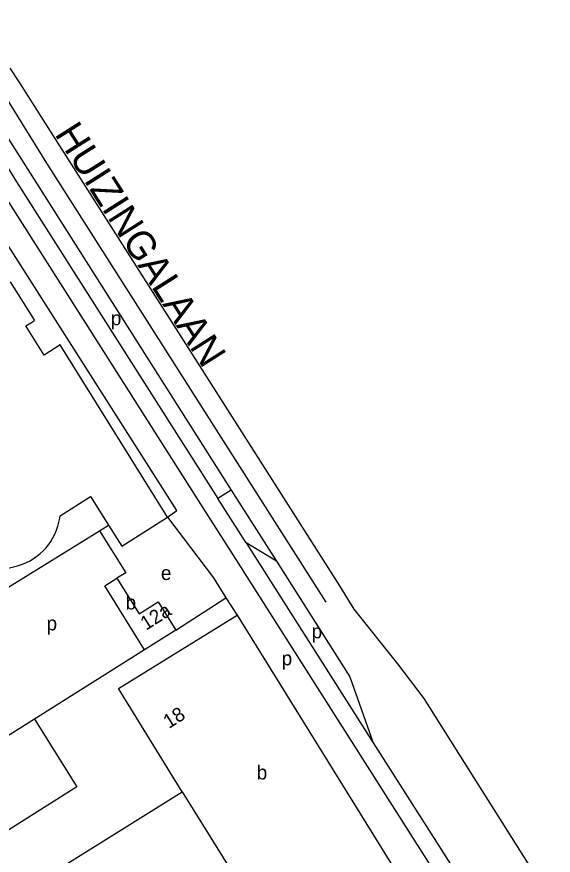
# Model space of a CAD drawing. Extents: x 158848 to 160613, y 385889 to 387762.
# Drawn here: x 159904.5 to 160056.5, y 387348.9 to 387586.4 of the extents above; entities that cross this region are included whole.
import ezdxf

# ---------------------------------------------------------------- set-up
doc = ezdxf.new("R2010")
doc.units = 0
for name, color, linetype in [('BLT_Basislijn', 7, 'Continuous'), ('BLT_Bebouwing', 7, 'Continuous'), ('BLT_Centroide', 7, 'Continuous'), ('BLT_Huisnummer', 7, 'Continuous'), ('BLT_Onderverdeling_panden', 7, 'Continuous'), ('BLT_Straatnaam_hoofdweg', 7, 'Continuous')]:
    doc.layers.add(name, color=color, linetype=linetype)

msp = doc.modelspace()

# ---------------------------------------------------------------- linework, layer by layer
at = {"layer": 'BLT_Basislijn'}
for p, q in [((159902.58, 387571.85), (159905.27, 387567.64)), ((159905.27, 387567.64), (159911.95, 387557.15)), ((159965.28, 387452.31), (159961.5, 387449.96)), ((159965.28, 387452.31), (159978.07, 387432.17)), ((159969.47, 387437.42), (159961.5, 387449.96)), ((159957.25, 387447.32), (159965.27, 387434.71)), ((159947.25, 387444.66), (159960.21, 387427.45)), ((159927.94, 387440.82), (159930.49, 387442.4)), ((159978.07, 387432.17), (159969.47, 387437.42)), ((159960.21, 387427.45), (159963.77, 387421.8)), ((159949.6, 387412.64), (159963.77, 387421.8)), ((159963.77, 387421.8), (159966.98, 387416.92)), ((159940.68, 387407.05), (159909.56, 387387.4)), ((159909.56, 387387.4), (159852.75, 387351.76))]:
    msp.add_line(p, q, dxfattribs=at)
for points in [[(159886.84, 387586.4), (159900.35, 387565.19), (159912.94, 387544.93), (159992.03, 387420.59)], [(159889.12, 387564.21), (159891.89, 387559.86), (159904.48, 387539.6), (159961.5, 387449.96)], [(159895.28, 387562.52), (159965.28, 387452.31)], [(159884.79, 387561.32), (159885.08, 387560.88), (159887.71, 387557.11), (159900.25, 387536.94), (159957.25, 387447.32)], [(159947.25, 387444.66), (159949.85, 387446.53), (159879, 387557.63)], [(159911.95, 387557.15), (159995.96, 387425.16), (160000, 387418.6)], [(159872.65, 387376.99), (159867.43, 387385.38), (159867.59, 387385.86), (159899.58, 387405.38), (159891.51, 387418.28), (159927.94, 387440.82)], [(159927.94, 387440.82), (159935.37, 387428.92), (159932.89, 387427.37)], [(159969.47, 387437.42), (160005.5, 387380.76)], [(159965.27, 387434.71), (160030.15, 387332.7), (160032.93, 387328.4)], [(159978.07, 387432.17), (159998.9, 387399.37), (160005.5, 387380.76)], [(160000, 387418.6), (160012.37, 387403.07), (160019.83, 387393.27), (160028.97, 387378.76), (160056.47, 387335.21)], [(159909.56, 387387.4), (159921.54, 387368.24)], [(160005.5, 387380.76), (160034.36, 387335.4), (160039.91, 387326.82), (160042.28, 387323.07)], [(159921.54, 387368.24), (159875.2, 387338.97)]]:
    msp.add_lwpolyline(points, dxfattribs=at)
at = {"layer": 'BLT_Bebouwing'}
for p, q in [((159902.68, 387511.33), (159909.52, 387500.38)), ((159930.49, 387442.4), (159934.28, 387436.4)), ((159966.98, 387416.92), (160011.68, 387344.61)), ((159949.6, 387412.64), (159940.68, 387407.05)), ((159917.9, 387346), (159951.4, 387366.82))]:
    msp.add_line(p, q, dxfattribs=at)
for points in [[(159947.25, 387444.66), (159916.79, 387493.44), (159912.29, 387490.58), (159907.08, 387498.82), (159908.93, 387500), (159909.52, 387500.38)], [(159916.79, 387445.04), (159925.39, 387450.5), (159930.49, 387442.4)], [(159912.72, 387435.86), (159913.46, 387436.8), (159914.14, 387437.78), (159914.75, 387438.81), (159915.28, 387439.87), (159915.75, 387440.97), (159916.14, 387442.09), (159916.46, 387443.24), (159916.69, 387444.41), (159916.79, 387445.04)], [(159934.28, 387436.4), (159943.03, 387441.97), (159947.25, 387444.66)], [(159905.05, 387430.93), (159906.15, 387431.32), (159907.23, 387431.78), (159908.28, 387432.32), (159909.28, 387432.92), (159910.24, 387433.59), (159911.15, 387434.33), (159912.02, 387435.12), (159912.72, 387435.86)], [(159896.68, 387430.53), (159897.82, 387430.33), (159898.98, 387430.21), (159900.13, 387430.18), (159901.29, 387430.22), (159902.44, 387430.34), (159903.58, 387430.55), (159904.7, 387430.83), (159905.05, 387430.93)], [(159940.68, 387407.05), (159929.42, 387425.19), (159932.89, 387427.37)], [(159932.89, 387427.37), (159939.21, 387417.31), (159944.56, 387420.68), (159949.6, 387412.64)], [(159951.4, 387366.82), (159933.3, 387396.1), (159966.98, 387416.92)]]:
    msp.add_lwpolyline(points, dxfattribs=at)
at = {"layer": 'BLT_Onderverdeling_panden'}
msp.add_line((159951.4, 387366.82), (159978.14, 387323.88), dxfattribs=at)

# ---------------------------------------------------------------- texts
at = {"layer": 'BLT_Centroide'}
for s, p in [('p', (159931.16, 387499.02)), ('e', (159945.35, 387426.84)), ('b', (159935.35, 387418.49)), ('p', (159912.96, 387412.58)), ('p', (159988.03, 387410.33)), ('p', (159979.54, 387402.67)), ('b', (159972.48, 387370.34))]:
    msp.add_text(s, height=4, dxfattribs=at).set_placement(p)
at = {"layer": 'BLT_Huisnummer'}
for s, p in [('12a', (159941.12, 387412.44)), ('18', (159947.59, 387384.62))]:
    msp.add_text(s, height=4, rotation=32.2399, dxfattribs=at).set_placement(p)
at = {"layer": 'BLT_Straatnaam_hoofdweg'}
msp.add_text('HUIZINGALAAN', height=8, rotation=302.4097, dxfattribs=at).set_placement((159915.07, 387553.19))

doc.saveas('drawing.dxf')
